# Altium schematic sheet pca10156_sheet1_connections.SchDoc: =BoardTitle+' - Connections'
size A3; Organization: Nordic Semiconductor; DocumentNumber: 1; SheetNumber: 1; SheetTotal: 8; CompanyName: Nordic Semiconductor; DocumentSize: A4
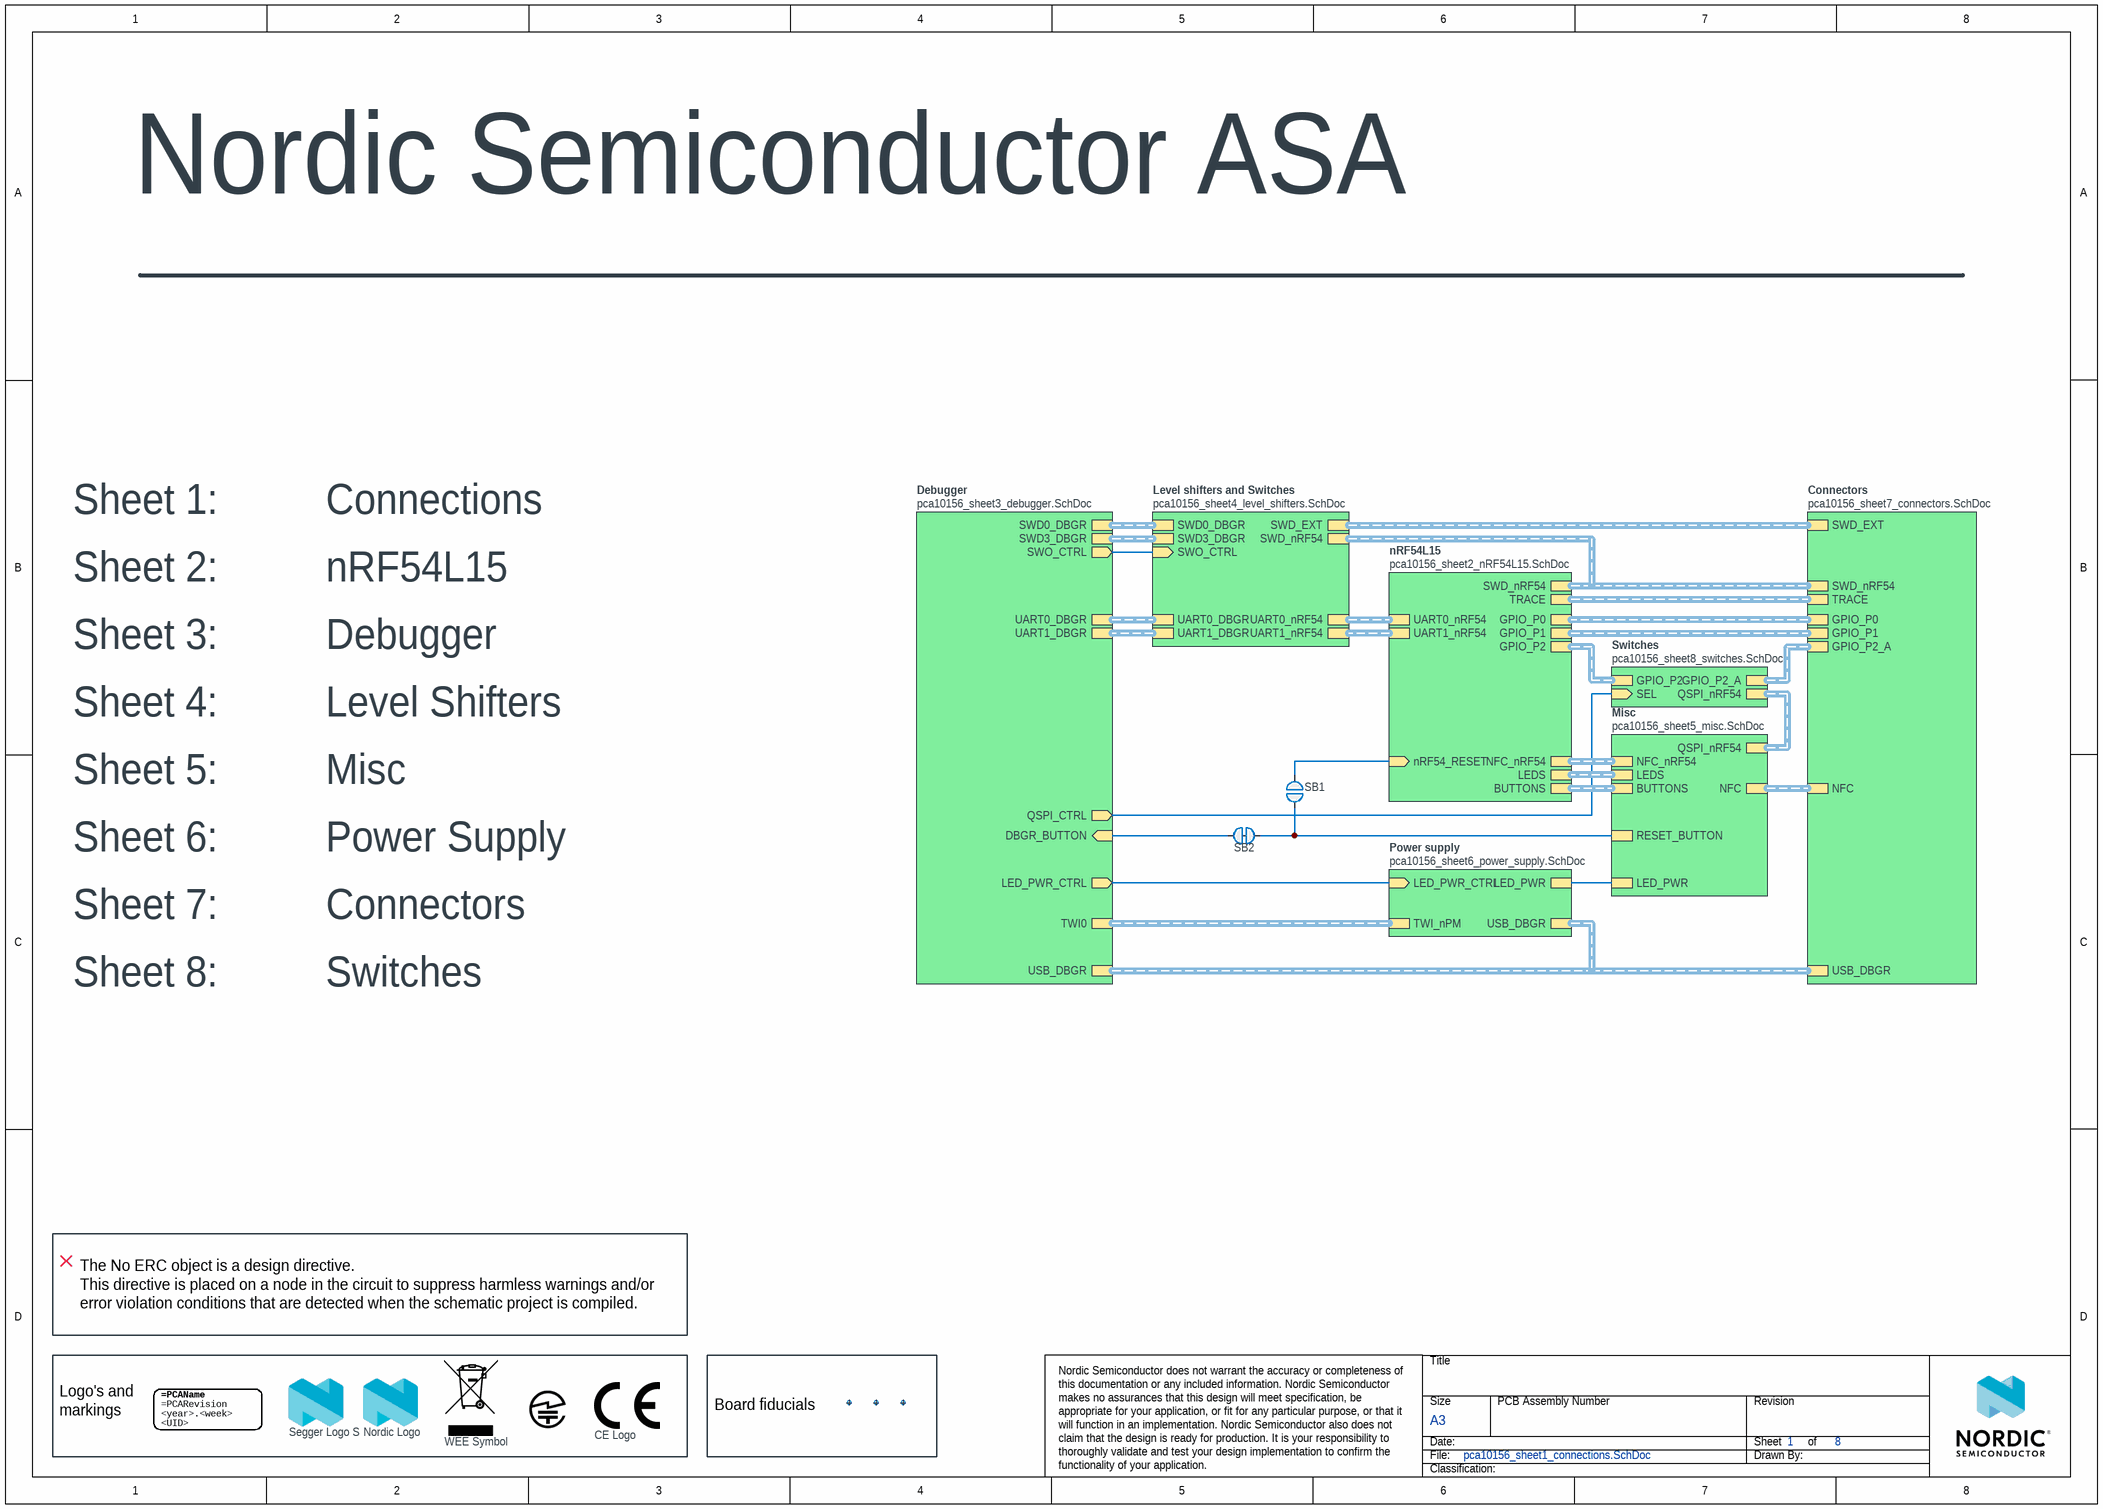
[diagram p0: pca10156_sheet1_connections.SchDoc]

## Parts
Fid1  Fiducial mark  [Fiducial]  (value not drawn)
Fid2  Fiducial mark  [Fiducial]  (value not drawn)
Fid3  Fiducial mark  [Fiducial]  (value not drawn)
LABEL1  12x12mm  [LabelSilk_12x12]  (value not drawn)
LOGO1  Nordic Logo  [NORDIC_LOGO_LYING]  (no BOM)
LOGO2  WEE Symbol  [WEE_3x4.5mm]  (no BOM)
LOGO3  Segger Logo S  [SEGGER_LOGO_S]  (no BOM)
LOGO4  CE Logo  [CE_logo]  (no BOM)
S1  Giteki Symbol  [Giteki]  (value not drawn)  (no BOM)
SB1  Solderbridge  [Solderbridge]  (value not drawn)  (no BOM)
SB2  Solderbridge  [Solderbridge_Shorted]  (value not drawn)  (net tie, no BOM)

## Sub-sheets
Connectors = pca10156_sheet7_connectors.SchDoc: SWD_nRF54 (harness SWD), TRACE (harness TRACE), NFC (harness NFC), SWD_EXT (harness SWD), GPIO_P0 (harness GPIO_P0), GPIO_P1 (harness GPIO_P1), USB_DBGR (harness USB), GPIO_P2_A (harness GPIO_P2)
Debugger = pca10156_sheet3_debugger.SchDoc: DBGR_BUTTON (in), SWD0_DBGR (harness SWD), UART0_DBGR (harness UART_DBGR), USB_DBGR (harness USB), UART1_DBGR (harness UART_DBGR), TWI0 (harness TWI), SWD3_DBGR (harness SWD), LED_PWR_CTRL (out), SWO_CTRL (out), QSPI_CTRL (out)
Level shifters and Switches = pca10156_sheet4_level_shifters.SchDoc: SWD0_DBGR (harness SWD), SWD_EXT (harness SWD), UART0_nRF54 (harness UART), UART1_nRF54 (harness UART), SWD3_DBGR (harness SWD), SWD_nRF54 (harness SWD), UART0_DBGR (harness UART_DBGR), UART1_DBGR (harness UART_DBGR), SWO_CTRL (in)
Misc = pca10156_sheet5_misc.SchDoc: NFC_nRF54 (harness NFC), NFC (harness NFC), BUTTONS (harness UI), LEDS (harness UI), RESET_BUTTON, LED_PWR, QSPI_nRF54
nRF54L15 = pca10156_sheet2_nRF54L15.SchDoc: BUTTONS (harness UI), LEDS (harness UI), TRACE (harness TRACE), NFC_nRF54 (harness NFC), GPIO_P0 (harness GPIO_P0), UART0_nRF54 (harness UART), GPIO_P1 (harness GPIO_P1), GPIO_P2 (harness GPIO_P2), UART1_nRF54 (harness UART), SWD_nRF54 (harness SWD), nRF54_RESET (in)
Power supply = pca10156_sheet6_power_supply.SchDoc: TWI_nPM (harness TWI), LED_PWR_CTRL (in), LED_PWR, USB_DBGR (harness USB)
Switches = pca10156_sheet8_switches.SchDoc: SEL (in), GPIO_P2 (harness GPIO_P2), QSPI_nRF54 (harness QSPI), GPIO_P2_A (harness GPIO_P2)

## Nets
NetSB1_1: SB1.1 ; sheet nRF54L15/nRF54_RESET
NetSB1_2: SB1.2 SB2.1 ; sheet Misc/RESET_BUTTON
NetSB2_2: SB2.2 ; sheet Debugger/DBGR_BUTTON
(unnamed): sheet Debugger/LED_PWR_CTRL, sheet Power supply/LED_PWR_CTRL
(unnamed): sheet Debugger/SWO_CTRL, sheet Level shifters and Switches/SWO_CTRL  [a separate net that carries the same name]
(unnamed): sheet Debugger/QSPI_CTRL, sheet Switches/SEL  [a separate net that carries the same name]
(unnamed): sheet Misc/LED_PWR, sheet Power supply/LED_PWR  [a separate net that carries the same name]

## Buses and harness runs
harness sheet Connectors/GPIO_P0 = sheet nRF54L15/GPIO_P0
harness sheet Connectors/GPIO_P1 = sheet nRF54L15/GPIO_P1
harness sheet Connectors/GPIO_P2_A = sheet Switches/GPIO_P2_A
harness sheet Connectors/NFC = sheet Misc/NFC
harness sheet Connectors/SWD_EXT = sheet Level shifters and Switches/SWD_EXT
harness sheet Connectors/SWD_nRF54 = sheet Level shifters and Switches/SWD_nRF54 = sheet nRF54L15/SWD_nRF54
harness sheet Connectors/TRACE = sheet nRF54L15/TRACE
harness sheet Connectors/USB_DBGR = sheet Debugger/USB_DBGR = sheet Power supply/USB_DBGR
harness sheet Debugger/SWD0_DBGR = sheet Level shifters and Switches/SWD0_DBGR
harness sheet Debugger/SWD3_DBGR = sheet Level shifters and Switches/SWD3_DBGR
harness sheet Debugger/TWI0 = sheet Power supply/TWI_nPM
harness sheet Debugger/UART0_DBGR = sheet Level shifters and Switches/UART0_DBGR
harness sheet Debugger/UART1_DBGR = sheet Level shifters and Switches/UART1_DBGR
harness sheet Level shifters and Switches/UART0_nRF54 = sheet nRF54L15/UART0_nRF54
harness sheet Level shifters and Switches/UART1_nRF54 = sheet nRF54L15/UART1_nRF54
harness sheet Misc/BUTTONS = sheet nRF54L15/BUTTONS
harness sheet Misc/LEDS = sheet nRF54L15/LEDS
harness sheet Misc/NFC_nRF54 = sheet nRF54L15/NFC_nRF54
harness sheet Misc/QSPI_nRF54 = sheet Switches/QSPI_nRF54
harness sheet nRF54L15/GPIO_P2 = sheet Switches/GPIO_P2

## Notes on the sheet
- Sheet 1:          Connections
- Sheet 2:          nRF54L15
- Sheet 4:          Level Shifters
- Sheet 3:          Debugger
- Sheet 5:          Misc
- Sheet 6:          Power Supply
- Sheet 7:          Connectors
- Sheet 8:          Switches
- The No ERC object is a design directive.
  This directive is placed on a node in the circuit to suppress harmless warnings and/or error violation conditions that are detected when the schematic project is compiled.
- (near LABEL1) Logo's and markings
- (near Fid1) Board fiducials

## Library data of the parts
Fid1-Fid3 = Fid-Mark: Manufacturer: N.A.; Part number NEMS: 100500073; Value: N.A.; Pad Count: 1; Component Status: Active; System: Connector
LABEL1 = Label_12x12: PCA version label, stick-on, 12x12mm; Manufacturer: Ellco Etikett; Manufacturer Part Number: A33512‐01; Part number NEMS: 101200028; Component Status: Active; Pad Count: 0; Note: N.A.
LOGO1 = Nordic Logo lying: Manufacturer: N.A.; Part number NEMS: 101100001; Component Status: Active; Pad Count: 0
LOGO2 = WEEE Symbol 3x4.5mm: WEEE Directive symbol; Manufacturer: N.A.; Part number NEMS: 101100006; Component Status: Active; Pad Count: 0
LOGO3 = Segger Logo S: Segger logo, small size; Manufacturer: N.A.; Part number NEMS: 101100004; Component Status: Active; Pad Count: 0
LOGO4 = CE_logo: CE (Conformité_Européenne) logo; Manufacturer: N.A.; Part number NEMS: 101100010; Component Status: Active; Pad Count: 0
S1 = Giteki Symbol: Manufacturer: N.A.; Part number NEMS: 101100011; Component Status: Active; Pad Count: 0
SB1 = Solderbridge: Manufacturer: N.A.; Part number NEMS: 100500458; Pad Count: 2; Component Status: Active; System: Connector
SB2 = Solderbridge Shorted: Shorted Solderbridge; Manufacturer: N.A.; Part number NEMS: 100500459; Pad Count: 2; Component Status: Active; System: Connector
